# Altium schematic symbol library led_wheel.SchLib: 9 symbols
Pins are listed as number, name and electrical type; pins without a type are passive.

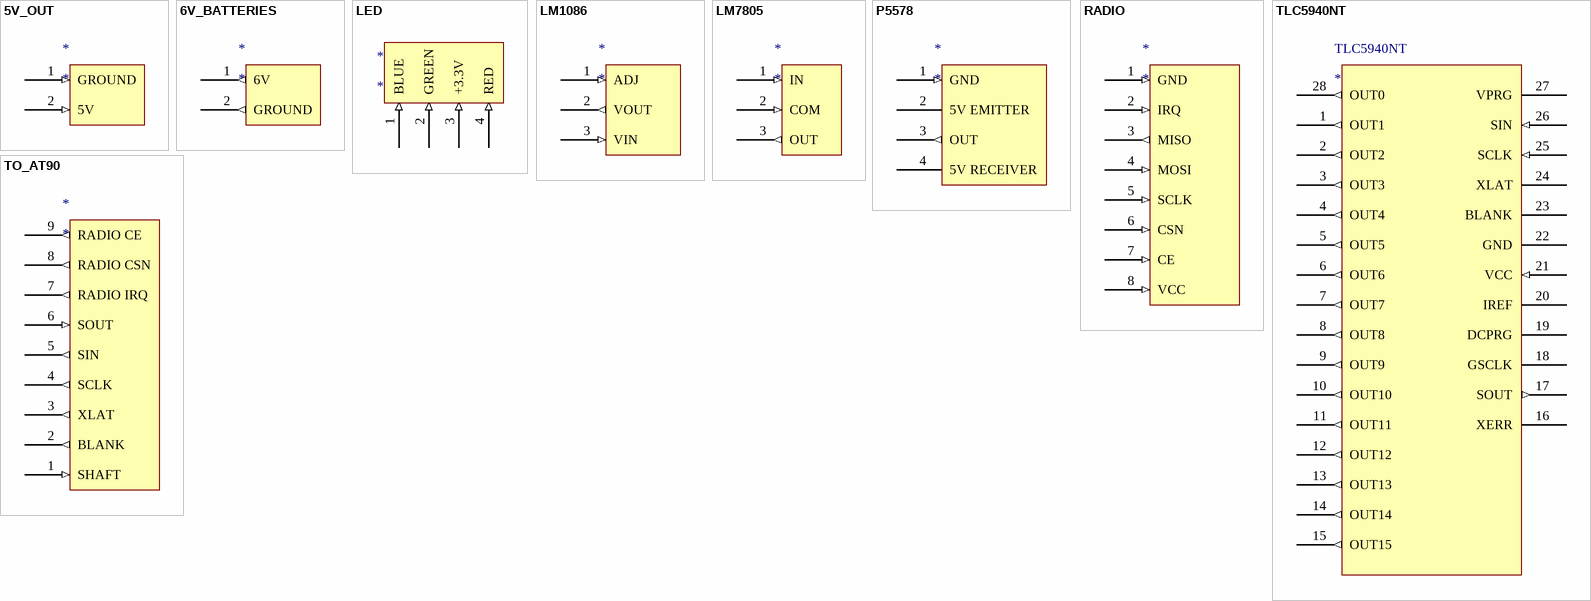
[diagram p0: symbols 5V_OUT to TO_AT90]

## 5V_OUT
designator *
footprint +5V OUT
pins: 1 GROUND (in), 2 5V (in)

## 6V_BATTERIES
designator *
footprint +6V BAT
pins: 1 6V (out), 2 GROUND (out)

## LED
designator *
footprint LED
pins: 1 BLUE (in), 2 GREEN (in), 3 +3.3V (in), 4 RED (in)

## LM1086
designator *
footprint LM1086
pins: 1 ADJ (in), 2 VOUT (out), 3 VIN (in)

## LM7805
designator *
footprint LM7805
pins: 1 IN (in), 2 COM (in), 3 OUT (out)

## P5578
designator *
footprint SHAFT
pins: 1 GND (in), 2 5V EMITTER, 3 OUT (out), 4 5V RECEIVER

## RADIO
designator *
footprint RADIO
pins: 1 GND (in), 2 IRQ (in), 3 MISO (out), 4 MOSI (in), 5 SCLK (in), 6 CSN (in), 7 CE (in), 8 VCC (in)

## TLC5940NT
designator TLC5940NT
footprint PDIP28
pins: 1 OUT1 (out), 2 OUT2 (out), 3 OUT3 (out), 4 OUT4 (out), 5 OUT5 (out), 6 OUT6 (out), 7 OUT7 (out), 8 OUT8 (out), 9 OUT9 (out), 10 OUT10 (out), 11 OUT11 (out), 12 OUT12 (out), 13 OUT13 (out), 14 OUT14 (out), 15 OUT15 (out), 16 XERR, 17 SOUT (out), 18 GSCLK, 19 DCPRG, 20 IREF, 21 VCC (in), 22 GND, 23 BLANK, 24 XLAT, 25 SCLK (in), 26 SIN (in), 27 VPRG, 28 OUT0 (out) "OUT1"

## TO_AT90
designator *
footprint TO AT90
pins: 1 SHAFT (in), 2 BLANK (out), 3 XLAT (out), 4 SCLK (out), 5 SIN (out), 6 SOUT (in), 7 RADIO IRQ (out), 8 RADIO CSN (out), 9 RADIO CE (out)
